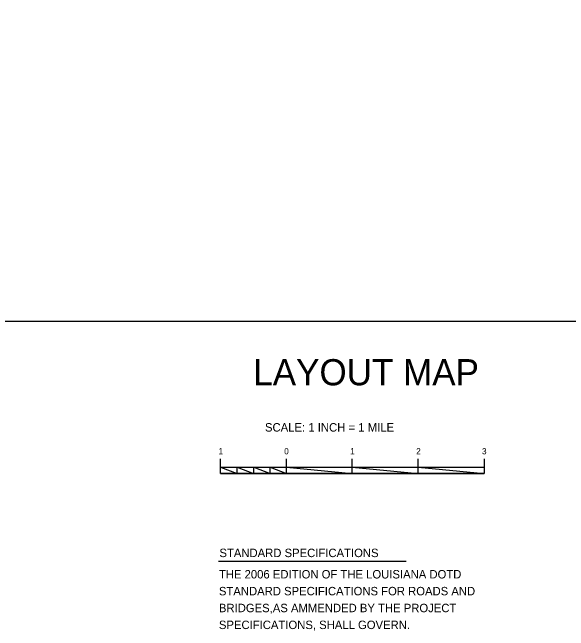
# Model space of a CAD drawing. Extents: x 0.19 to 2.82, y 0.04 to 1.79.
# Drawn here: x 1.075 to 1.779, y 0.167 to 0.949 of the extents above; entities that cross this region are included whole.
import ezdxf

# ---------------------------------------------------------------- set-up
doc = ezdxf.new("R2010")
doc.units = 0
doc.layers.add('Layout Map Info', color=7, linetype='Continuous')
doc.layers.add('Standard Info', color=7, linetype='Continuous')

msp = doc.modelspace()

# ---------------------------------------------------------------- linework, layer by layer
at = {"layer": 'Layout Map Info'}
msp.add_lwpolyline([(0.90383, 0.55854), (2.1045, 0.55854), (2.1045, 1.08488), (0.90383, 1.08488)], close=True, dxfattribs=at)
at = {"layer": 'Standard Info'}
for p, q in [((1.33813, 0.36599), (1.33813, 0.38432)), ((1.42146, 0.36599), (1.42146, 0.38432)), ((1.5048, 0.36599), (1.5048, 0.38432)), ((1.58813, 0.36599), (1.58813, 0.38432)), ((1.67146, 0.38432), (1.67146, 0.36599)), ((1.33813, 0.37382), (1.67146, 0.37382)), ((1.33813, 0.36599), (1.67146, 0.36599)), ((1.33526, 0.25493), (1.57306, 0.25493))]:
    msp.add_line(p, q, dxfattribs=at)
for points in [[(1.33813, 0.36599), (1.33813, 0.37382), (1.35888, 0.36599)], [(1.35896, 0.36599), (1.35896, 0.37382), (1.3798, 0.36599)], [(1.37996, 0.36599), (1.37996, 0.37382), (1.40071, 0.36599)], [(1.40063, 0.36599), (1.40063, 0.37382), (1.42146, 0.36599)], [(1.42146, 0.36599), (1.42146, 0.37382), (1.5048, 0.36599)], [(1.5048, 0.36599), (1.5048, 0.37382), (1.58813, 0.36599)], [(1.58813, 0.36599), (1.58813, 0.37382), (1.67146, 0.36599)]]:
    msp.add_lwpolyline(points, close=True, dxfattribs=at)

# ---------------------------------------------------------------- texts
for s, height, p in [('LAYOUT MAP', 0.03313, (1.37947, 0.47738)), ('SCALE: 1 INCH = 1 MILE', 0.0107, (1.39425, 0.41884)), ('1', 0.0078, (1.33539, 0.39008)), ('0', 0.0078, (1.41856, 0.39008)), ('1', 0.0078, (1.50206, 0.39008)), ('2', 0.0078, (1.5856, 0.39008)), ('3', 0.0078, (1.6689, 0.39008)), ('STANDARD SPECIFICATIONS', 0.01067, (1.33661, 0.26)), ('THE 2006 EDITION OF THE LOUISIANA DOTD ', 0.01067, (1.33598, 0.23297)), ('STANDARD SPECIFICATIONS FOR ROADS AND ', 0.01067, (1.33598, 0.21163)), ('BRIDGES,AS AMMENDED BY THE PROJECT ', 0.01067, (1.33598, 0.19029)), ('SPECIFICATIONS, SHALL GOVERN. ', 0.01067, (1.33598, 0.16895))]:
    msp.add_text(s, height=height, dxfattribs=at).set_placement(p)

doc.saveas('drawing.dxf')
